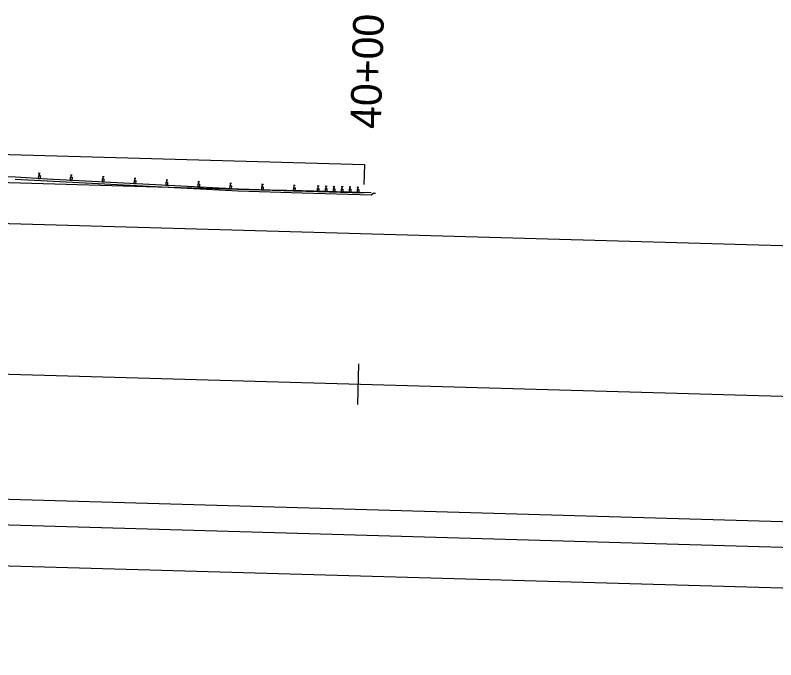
# Model space of a CAD drawing. Extents: x 976639 to 985448, y 1524031 to 1526806.
# Drawn here: x 982751.8 to 982900.8, y 1526267.1 to 1526393.3 of the extents above; entities that cross this region are included whole.
import ezdxf

# ---------------------------------------------------------------- set-up
doc = ezdxf.new("R2010")
doc.units = 0
for name, color, linetype in [('B_Steel', 7, 'Continuous'), ('R_Horz Alg', 7, 'Continuous'), ('R_Horz Alg Annot', 7, 'Continuous'), ('R_Proposed Road_Lane', 7, 'Continuous'), ('R_Proposed Road_Shoulder', 7, 'Continuous'), ('S_WORKING_LINES', 7, 'Continuous')]:
    doc.layers.add(name, color=color, linetype=linetype)

msp = doc.modelspace()

# ---------------------------------------------------------------- linework, layer by layer
at = {"layer": 'B_Steel'}
for p, q in [((982751.86, 1526361.53), (982745.61, 1526361.86)), ((982756.39, 1526361.88), (982756.36, 1526361.29)), ((982756.39, 1526361.89), (982756.54, 1526361.88)), ((982756.39, 1526361.89), (982756.39, 1526361.88)), ((982756.39, 1526361.88), (982756.72, 1526361.86)), ((982756.42, 1526362.38), (982756.75, 1526362.36)), ((982756.42, 1526362.38), (982756.42, 1526362.36)), ((982756.42, 1526362.36), (982756.57, 1526362.35)), ((982756.55, 1526361.89), (982756.57, 1526362.34)), ((982756.57, 1526361.89), (982756.59, 1526362.34)), ((982756.57, 1526361.88), (982756.73, 1526361.87)), ((982756.6, 1526362.35), (982756.75, 1526362.34)), ((982756.72, 1526361.86), (982756.69, 1526361.28)), ((982756.73, 1526361.87), (982756.72, 1526361.86)), ((982756.75, 1526362.36), (982756.75, 1526362.34)), ((982762.66, 1526362.05), (982762.99, 1526362.03)), ((982762.66, 1526362.05), (982762.66, 1526362.03)), ((982762.66, 1526362.03), (982762.81, 1526362.02)), ((982762.79, 1526361.56), (982762.82, 1526362.01)), ((982762.81, 1526361.56), (982762.83, 1526362.01)), ((982762.84, 1526362.02), (982762.99, 1526362.01)), ((982762.99, 1526362.03), (982762.99, 1526362.01)), ((982768.9, 1526361.72), (982769.23, 1526361.7)), ((982768.9, 1526361.72), (982768.9, 1526361.7)), ((982768.9, 1526361.7), (982769.05, 1526361.69)), ((982769.03, 1526361.23), (982769.06, 1526361.68)), ((982769.05, 1526361.23), (982769.07, 1526361.68)), ((982769.08, 1526361.69), (982769.23, 1526361.68)), ((982769.23, 1526361.7), (982769.23, 1526361.68)), ((982758.08, 1526360.79), (982751.83, 1526361.12)), ((982758.1, 1526361.2), (982751.86, 1526361.53)), ((982756.36, 1526361.29), (982756.69, 1526361.28)), ((982764.32, 1526360.46), (982758.08, 1526360.79)), ((982764.34, 1526360.87), (982758.1, 1526361.2)), ((982762.63, 1526361.55), (982762.6, 1526360.96)), ((982762.6, 1526360.96), (982762.94, 1526360.95)), ((982762.63, 1526361.56), (982762.78, 1526361.55)), ((982762.63, 1526361.56), (982762.63, 1526361.55)), ((982762.63, 1526361.55), (982762.97, 1526361.53)), ((982762.82, 1526361.55), (982762.97, 1526361.54)), ((982762.97, 1526361.53), (982762.94, 1526360.95)), ((982762.97, 1526361.54), (982762.97, 1526361.53)), ((982770.56, 1526360.13), (982764.32, 1526360.46)), ((982770.58, 1526360.54), (982764.34, 1526360.87)), ((982768.87, 1526361.22), (982768.84, 1526360.63)), ((982768.84, 1526360.63), (982769.18, 1526360.62)), ((982768.88, 1526361.23), (982768.87, 1526361.22)), ((982768.87, 1526361.22), (982769.21, 1526361.2)), ((982768.88, 1526361.23), (982769.03, 1526361.22)), ((982769.06, 1526361.22), (982769.21, 1526361.21)), ((982769.21, 1526361.2), (982769.18, 1526360.62)), ((982769.21, 1526361.21), (982769.21, 1526361.2)), ((982776.82, 1526360.21), (982770.58, 1526360.54)), ((982775.12, 1526360.89), (982775.09, 1526360.3)), ((982775.09, 1526360.3), (982775.42, 1526360.29)), ((982775.12, 1526360.9), (982775.27, 1526360.89)), ((982775.12, 1526360.9), (982775.12, 1526360.89)), ((982775.12, 1526360.89), (982775.45, 1526360.87)), ((982775.14, 1526361.39), (982775.47, 1526361.37)), ((982775.14, 1526361.39), (982775.14, 1526361.37)), ((982775.14, 1526361.37), (982775.29, 1526361.36)), ((982775.27, 1526360.9), (982775.3, 1526361.35)), ((982775.29, 1526360.9), (982775.31, 1526361.35)), ((982775.3, 1526360.89), (982775.45, 1526360.88)), ((982775.32, 1526361.36), (982775.47, 1526361.35)), ((982775.45, 1526360.87), (982775.42, 1526360.29)), ((982775.45, 1526360.88), (982775.45, 1526360.87)), ((982775.47, 1526361.37), (982775.47, 1526361.35)), ((982783.06, 1526359.88), (982776.82, 1526360.21)), ((982781.36, 1526360.56), (982781.33, 1526359.97)), ((982781.36, 1526360.57), (982781.51, 1526360.56)), ((982781.36, 1526360.57), (982781.36, 1526360.56)), ((982781.36, 1526360.56), (982781.69, 1526360.54)), ((982781.38, 1526361.06), (982781.72, 1526361.04)), ((982781.38, 1526361.06), (982781.38, 1526361.04)), ((982781.38, 1526361.04), (982781.53, 1526361.03)), ((982781.52, 1526360.57), (982781.54, 1526361.02)), ((982781.53, 1526360.57), (982781.56, 1526361.02)), ((982781.54, 1526360.56), (982781.69, 1526360.55)), ((982781.56, 1526361.03), (982781.72, 1526361.02)), ((982781.69, 1526360.54), (982781.66, 1526359.96)), ((982781.69, 1526360.55), (982781.69, 1526360.54)), ((982781.72, 1526361.04), (982781.72, 1526361.02)), ((982787.6, 1526360.23), (982787.57, 1526359.64)), ((982787.6, 1526360.24), (982787.75, 1526360.23)), ((982787.6, 1526360.24), (982787.6, 1526360.23)), ((982787.6, 1526360.23), (982787.93, 1526360.21)), ((982787.62, 1526360.73), (982787.96, 1526360.71)), ((982787.62, 1526360.73), (982787.62, 1526360.71)), ((982787.62, 1526360.71), (982787.77, 1526360.7)), ((982787.76, 1526360.24), (982787.78, 1526360.69)), ((982787.77, 1526360.24), (982787.8, 1526360.69)), ((982787.78, 1526360.23), (982787.93, 1526360.22)), ((982787.81, 1526360.7), (982787.96, 1526360.69)), ((982787.93, 1526360.21), (982787.9, 1526359.63)), ((982787.93, 1526360.22), (982787.93, 1526360.21)), ((982787.96, 1526360.71), (982787.96, 1526360.69)), ((982793.87, 1526360.4), (982794.2, 1526360.38)), ((982793.87, 1526360.4), (982793.87, 1526360.38)), ((982793.87, 1526360.38), (982794.02, 1526360.37)), ((982794, 1526359.91), (982794.02, 1526360.36)), ((982794.01, 1526359.91), (982794.04, 1526360.36)), ((982794.05, 1526360.37), (982794.2, 1526360.36)), ((982794.2, 1526360.38), (982794.2, 1526360.36)), ((982800.08, 1526360.18), (982800.41, 1526360.17)), ((982800.08, 1526360.18), (982800.08, 1526360.16)), ((982776.8, 1526359.8), (982770.56, 1526360.13)), ((982783.04, 1526359.47), (982776.8, 1526359.8)), ((982781.33, 1526359.97), (982781.66, 1526359.96)), ((982789.28, 1526359.14), (982783.04, 1526359.47)), ((982789.3, 1526359.55), (982783.06, 1526359.88)), ((982787.57, 1526359.64), (982787.9, 1526359.63)), ((982795.52, 1526358.81), (982789.28, 1526359.14)), ((982795.55, 1526359.22), (982789.3, 1526359.55)), ((982793.84, 1526359.9), (982793.81, 1526359.31)), ((982793.81, 1526359.31), (982794.14, 1526359.3)), ((982793.84, 1526359.91), (982793.99, 1526359.9)), ((982793.84, 1526359.91), (982793.84, 1526359.9)), ((982793.84, 1526359.9), (982794.17, 1526359.88)), ((982794.02, 1526359.9), (982794.17, 1526359.89)), ((982794.17, 1526359.88), (982794.14, 1526359.3)), ((982794.17, 1526359.89), (982794.17, 1526359.88)), ((982801.77, 1526358.63), (982795.52, 1526358.81)), ((982801.78, 1526359.04), (982795.54, 1526359.22)), ((982800.06, 1526359.68), (982800.04, 1526359.09)), ((982800.04, 1526359.09), (982800.38, 1526359.08)), ((982800.06, 1526359.69), (982800.21, 1526359.69)), ((982800.06, 1526359.69), (982800.06, 1526359.68)), ((982800.06, 1526359.68), (982800.39, 1526359.67)), ((982800.08, 1526360.16), (982800.23, 1526360.16)), ((982800.22, 1526359.69), (982800.23, 1526360.15)), ((982800.24, 1526359.69), (982800.25, 1526360.15)), ((982800.24, 1526359.69), (982800.39, 1526359.68)), ((982800.26, 1526360.15), (982800.41, 1526360.15)), ((982800.39, 1526359.67), (982800.38, 1526359.08)), ((982800.39, 1526359.68), (982800.39, 1526359.67)), ((982800.41, 1526360.17), (982800.41, 1526360.15)), ((982808.03, 1526358.86), (982801.78, 1526359.04)), ((982806.31, 1526359.5), (982806.29, 1526358.91)), ((982806.29, 1526358.91), (982806.62, 1526358.9)), ((982806.31, 1526359.51), (982806.46, 1526359.51)), ((982806.31, 1526359.51), (982806.31, 1526359.5)), ((982806.31, 1526359.5), (982806.64, 1526359.49)), ((982806.32, 1526360), (982806.66, 1526359.99)), ((982806.32, 1526360), (982806.32, 1526359.98)), ((982806.32, 1526359.98), (982806.47, 1526359.98)), ((982806.47, 1526359.51), (982806.48, 1526359.97)), ((982806.48, 1526359.51), (982806.5, 1526359.97)), ((982806.49, 1526359.51), (982806.64, 1526359.5)), ((982806.5, 1526359.98), (982806.66, 1526359.97)), ((982806.64, 1526359.49), (982806.62, 1526358.9)), ((982806.64, 1526359.5), (982806.64, 1526359.49)), ((982806.66, 1526359.99), (982806.66, 1526359.97)), ((982821.56, 1526358.48), (982808.03, 1526358.86)), ((982810.99, 1526359.36), (982810.97, 1526358.78)), ((982810.99, 1526359.38), (982811.14, 1526359.37)), ((982810.99, 1526359.38), (982810.99, 1526359.36)), ((982810.99, 1526359.36), (982811.32, 1526359.35)), ((982811, 1526359.86), (982811.34, 1526359.85)), ((982811, 1526359.86), (982811, 1526359.85)), ((982811, 1526359.85), (982811.15, 1526359.84)), ((982811.15, 1526359.38), (982811.16, 1526359.83)), ((982811.16, 1526359.38), (982811.18, 1526359.83)), ((982811.17, 1526359.37), (982811.32, 1526359.37)), ((982811.19, 1526359.84), (982811.34, 1526359.84)), ((982811.32, 1526359.35), (982811.31, 1526358.77)), ((982811.32, 1526359.37), (982811.32, 1526359.35)), ((982811.34, 1526359.85), (982811.34, 1526359.84)), ((982812.55, 1526359.32), (982812.53, 1526358.74)), ((982812.55, 1526359.33), (982812.7, 1526359.33)), ((982812.55, 1526359.33), (982812.55, 1526359.32)), ((982812.55, 1526359.32), (982812.88, 1526359.31)), ((982812.57, 1526359.82), (982812.9, 1526359.81)), ((982812.57, 1526359.82), (982812.57, 1526359.8)), ((982812.57, 1526359.8), (982812.72, 1526359.8)), ((982812.71, 1526359.34), (982812.72, 1526359.79)), ((982812.73, 1526359.34), (982812.74, 1526359.79)), ((982812.73, 1526359.33), (982812.88, 1526359.32)), ((982812.75, 1526359.8), (982812.9, 1526359.79)), ((982812.88, 1526359.31), (982812.87, 1526358.73)), ((982812.88, 1526359.32), (982812.88, 1526359.31)), ((982812.9, 1526359.81), (982812.9, 1526359.79)), ((982814.11, 1526359.27), (982814.1, 1526358.69)), ((982814.11, 1526359.29), (982814.26, 1526359.28)), ((982814.11, 1526359.29), (982814.11, 1526359.27)), ((982814.11, 1526359.27), (982814.45, 1526359.26)), ((982814.13, 1526359.77), (982814.46, 1526359.76)), ((982814.13, 1526359.77), (982814.13, 1526359.76)), ((982814.13, 1526359.76), (982814.28, 1526359.75)), ((982814.27, 1526359.29), (982814.29, 1526359.75)), ((982814.29, 1526359.29), (982814.3, 1526359.74)), ((982814.3, 1526359.28), (982814.45, 1526359.28)), ((982814.31, 1526359.75), (982814.46, 1526359.75)), ((982814.45, 1526359.26), (982814.43, 1526358.68)), ((982814.45, 1526359.28), (982814.45, 1526359.26)), ((982814.46, 1526359.76), (982814.46, 1526359.75)), ((982815.67, 1526359.23), (982815.66, 1526358.65)), ((982815.68, 1526359.24), (982815.67, 1526359.23)), ((982815.67, 1526359.23), (982816.01, 1526359.22)), ((982815.68, 1526359.24), (982815.83, 1526359.24)), ((982815.69, 1526359.73), (982816.02, 1526359.72)), ((982815.69, 1526359.73), (982815.69, 1526359.71)), ((982815.69, 1526359.71), (982815.84, 1526359.71)), ((982815.83, 1526359.25), (982815.85, 1526359.7)), ((982815.85, 1526359.25), (982815.86, 1526359.7)), ((982815.86, 1526359.24), (982816.01, 1526359.23)), ((982815.87, 1526359.71), (982816.02, 1526359.7)), ((982816.01, 1526359.22), (982815.99, 1526358.64)), ((982816.01, 1526359.23), (982816.01, 1526359.22)), ((982816.02, 1526359.72), (982816.02, 1526359.7)), ((982817.24, 1526359.18), (982817.22, 1526358.6)), ((982817.24, 1526359.2), (982817.39, 1526359.2)), ((982817.24, 1526359.2), (982817.24, 1526359.18)), ((982817.24, 1526359.18), (982817.57, 1526359.17)), ((982817.25, 1526359.68), (982817.58, 1526359.67)), ((982817.25, 1526359.68), (982817.25, 1526359.67)), ((982817.25, 1526359.67), (982817.4, 1526359.66)), ((982817.4, 1526359.2), (982817.41, 1526359.66)), ((982817.41, 1526359.2), (982817.42, 1526359.66)), ((982817.42, 1526359.19), (982817.57, 1526359.19)), ((982817.43, 1526359.66), (982817.58, 1526359.66)), ((982817.57, 1526359.17), (982817.55, 1526358.59)), ((982817.57, 1526359.19), (982817.57, 1526359.17)), ((982817.58, 1526359.67), (982817.58, 1526359.66)), ((982818.8, 1526359.14), (982818.78, 1526358.56)), ((982818.8, 1526359.15), (982818.95, 1526359.15)), ((982818.8, 1526359.15), (982818.8, 1526359.14)), ((982818.8, 1526359.14), (982819.13, 1526359.13)), ((982818.81, 1526359.64), (982819.15, 1526359.63)), ((982818.81, 1526359.64), (982818.81, 1526359.62)), ((982818.81, 1526359.62), (982818.96, 1526359.62)), ((982818.96, 1526359.16), (982818.97, 1526359.61)), ((982818.97, 1526359.16), (982818.99, 1526359.61)), ((982818.98, 1526359.15), (982819.13, 1526359.15)), ((982818.99, 1526359.62), (982819.15, 1526359.61)), ((982819.13, 1526359.13), (982819.11, 1526358.55)), ((982819.13, 1526359.15), (982819.13, 1526359.13)), ((982819.15, 1526359.63), (982819.15, 1526359.61)), ((982808.02, 1526358.45), (982801.77, 1526358.63)), ((982821.55, 1526358.06), (982808.02, 1526358.45)), ((982822.1, 1526358.42), (982821.55, 1526358.06)), ((982822.1, 1526358.42), (982822.4, 1526358.42)), ((982822.4, 1526358.42), (982822.41, 1526358.45))]:
    msp.add_line(p, q, dxfattribs=at)
for centre, start, end in [((982811.14, 1526359.38), 268.3578, 358.3578), ((982811.15, 1526359.83), 358.3578, 88.3578), ((982811.17, 1526359.38), 178.3578, 268.3578), ((982811.19, 1526359.83), 88.3578, 178.3578), ((982812.7, 1526359.34), 268.3578, 358.3578), ((982812.72, 1526359.79), 358.3578, 88.3578), ((982812.73, 1526359.34), 178.3578, 268.3578), ((982812.75, 1526359.79), 88.3578, 178.3578), ((982814.26, 1526359.29), 268.3578, 358.3578), ((982814.28, 1526359.75), 358.3578, 88.3578), ((982814.3, 1526359.29), 178.3578, 268.3578), ((982814.31, 1526359.74), 88.3578, 178.3578), ((982815.83, 1526359.25), 268.3578, 358.3578), ((982815.84, 1526359.7), 358.3578, 88.3578), ((982815.86, 1526359.25), 178.3578, 268.3578), ((982815.87, 1526359.7), 88.3578, 178.3578), ((982817.39, 1526359.2), 268.3578, 358.3578), ((982817.4, 1526359.66), 358.3578, 88.3578), ((982817.42, 1526359.2), 178.3578, 268.3578), ((982817.43, 1526359.65), 88.3578, 178.3578), ((982818.95, 1526359.16), 268.3578, 358.3578), ((982818.96, 1526359.61), 358.3578, 88.3578), ((982818.98, 1526359.16), 178.3578, 268.3578), ((982818.99, 1526359.61), 88.3578, 178.3578)]:
    msp.add_arc(centre, 0.008, start, end, dxfattribs=at)
at = {"layer": 'R_Horz Alg'}
msp.add_line((981519.52, 1526358.29), (984298.38, 1526278.62), dxfattribs=at)
at = {"layer": 'R_Horz Alg Annot'}
msp.add_lwpolyline([(982819.1, 1526325.03), (982818.87, 1526317.04)], dxfattribs=at)
at = {"layer": 'R_Proposed Road_Lane'}
for p, q in [((982667.01, 1526368.41), (982820.22, 1526364.02)), ((982820.22, 1526364.02), (982820.11, 1526360.1)), ((982420, 1526361.99), (983394.6, 1526334.04)), ((982418.3, 1526303.01), (983392.9, 1526275.07))]:
    msp.add_line(p, q, dxfattribs=at)
at = {"layer": 'R_Proposed Road_Shoulder'}
for p, q in [((982420.22, 1526369.98), (982820.06, 1526358.52)), ((982418.08, 1526295.01), (983392.67, 1526267.07))]:
    msp.add_line(p, q, dxfattribs=at)
at = {"layer": 'S_WORKING_LINES'}
msp.add_line((982635.72, 1526301.78), (983189.69, 1526285.9), dxfattribs=at)

# ---------------------------------------------------------------- texts
at = {"layer": 'R_Horz Alg Annot'}
msp.add_text('40+00', height=6, rotation=88.3578, dxfattribs=at).set_placement((982823.42, 1526370.93))

doc.saveas('drawing.dxf')
